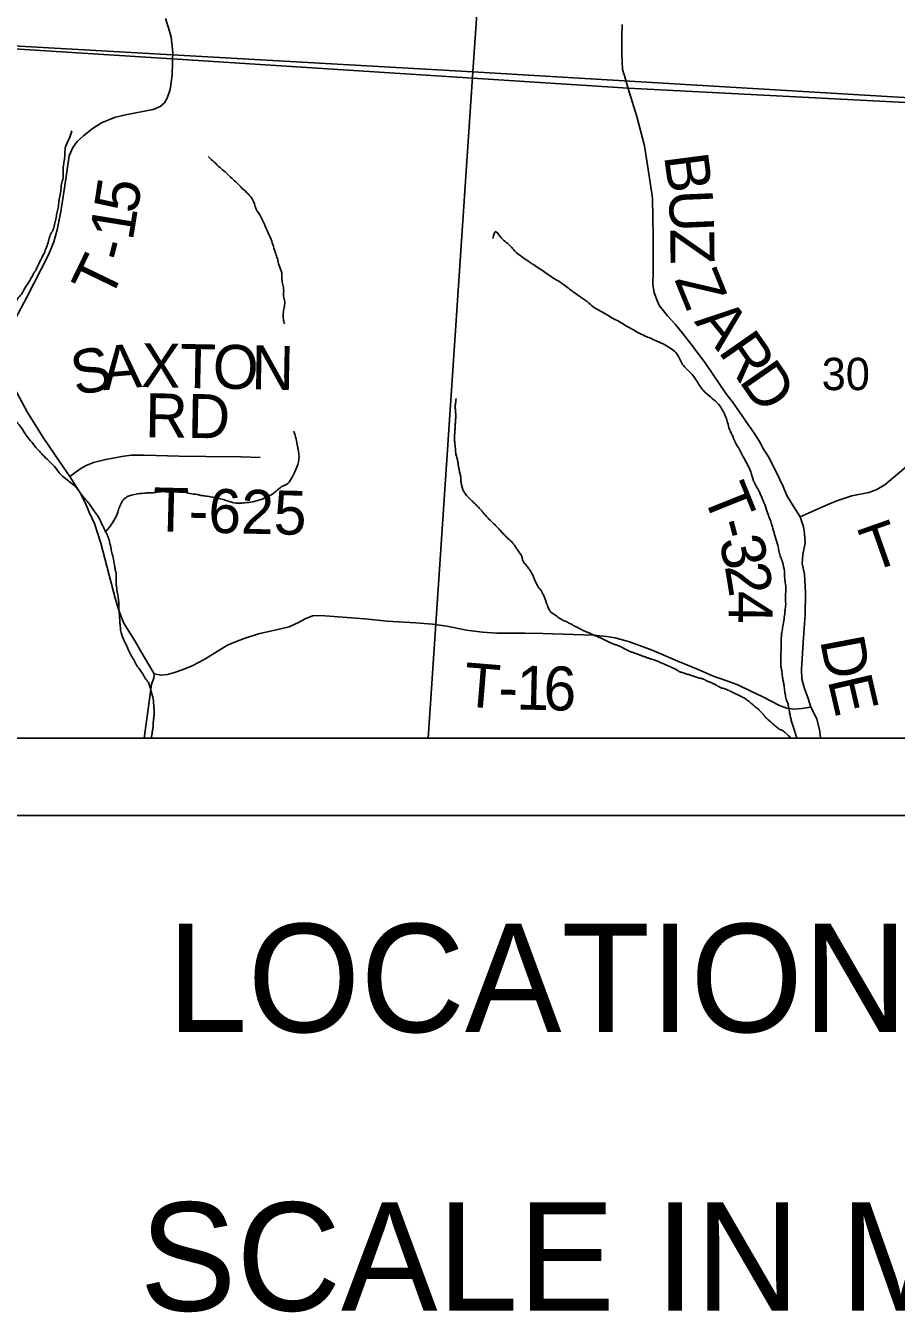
# Model space of a CAD drawing. Extents: x -13.7 to 34, y 0 to 32.3.
# Drawn here: x 26.069 to 27.194, y 13.358 to 15.02 of the extents above; entities that cross this region are included whole.
import ezdxf

# ---------------------------------------------------------------- set-up
doc = ezdxf.new("R2010")
doc.units = 0
for name, color, linetype in [('GM_X_Corporation', 7, 'Continuous'), ('GM_X_Minor_River', 7, 'Continuous'), ('GM_X_Section_Text', 7, 'Continuous'), ('GM_X_Township_Road', 7, 'Continuous'), ('GM_X_Township_Road_Text', 7, 'Continuous'), ('SH_Data', 7, 'Continuous'), ('SH_Text', 7, 'Continuous')]:
    doc.layers.add(name, color=color, linetype=linetype)

msp = doc.modelspace()

# ---------------------------------------------------------------- linework, layer by layer
at = {"layer": 'GM_X_Corporation'}
for points in [[(25.6857, 16.1459), (25.6733, 15.948), (25.6502, 15.5943), (25.6174, 15.0182), (25.5491, 14.1), (30.3167, 14.1)], [(25.6857, 16.1459), (25.6733, 15.948), (25.6502, 15.5943), (25.6174, 15.0182), (26.2581, 14.9774), (26.847, 14.9399), (27.6886, 14.8962), (28.6553, 14.8354)]]:
    msp.add_lwpolyline(points, dxfattribs=at)
for points in [[(25.6876, 16.0444), (26.7165, 15.9781), (26.6464, 14.9606), (25.6185, 15.0191)], [(26.7165, 15.9781), (27.73, 15.9158), (27.6593, 14.9006), (26.6464, 14.9606)], [(25.5491, 14.1), (30.3167, 14.1), (30.3167, 14.7354), (29.7019, 14.7755), (28.6553, 14.8354), (27.6886, 14.8962), (26.847, 14.9399), (26.2581, 14.9774), (25.6174, 15.0182)], [(25.5561, 14.1), (26.5888, 14.1), (26.6464, 14.9606), (25.6185, 15.0191)], [(26.5888, 14.1), (27.607, 14.1), (27.6593, 14.9006), (26.6464, 14.9606)]]:
    msp.add_lwpolyline(points, close=True, dxfattribs=at)
at = {"layer": 'GM_X_Minor_River'}
for points in [[(26.1283, 14.8845), (26.1244, 14.8735), (26.1202, 14.864), (26.1194, 14.8561), (26.119, 14.8496), (26.1178, 14.8424), (26.117, 14.8321), (26.1169, 14.8234), (26.115, 14.8158), (26.1142, 14.8086), (26.1126, 14.7999), (26.1114, 14.7915), (26.1106, 14.785), (26.109, 14.7782), (26.1078, 14.7706), (26.1059, 14.7634), (26.1039, 14.7562), (26.1005, 14.7498), (26.0982, 14.7422), (26.0955, 14.7342), (26.0924, 14.7262), (26.0866, 14.7149), (26.082, 14.7054), (26.0785, 14.6993), (26.0739, 14.691), (26.0686, 14.6827), (26.0632, 14.6736), (26.0582, 14.6675), (26.054, 14.66), (26.0483, 14.6524), (26.0437, 14.6459), (26.0406, 14.6395), (26.0371, 14.6334), (26.0337, 14.6255), (26.0302, 14.6187), (26.0271, 14.6099), (26.0248, 14.6035), (26.0229, 14.5963), (26.0217, 14.5887), (26.0212, 14.5799), (26.0235, 14.5731), (26.0272, 14.5628), (26.0317, 14.554), (26.0366, 14.5472), (26.0392, 14.5407), (26.0429, 14.5327), (26.0467, 14.5251), (26.0515, 14.5163), (26.0572, 14.5083), (26.0628, 14.5014), (26.0681, 14.493), (26.0733, 14.4861), (26.0805, 14.4773), (26.0865, 14.4705), (26.0925, 14.464), (26.1005, 14.4563), (26.1076, 14.4487), (26.1121, 14.4426), (26.1204, 14.4349), (26.1272, 14.4296), (26.1336, 14.4242), (26.1385, 14.4177), (26.1449, 14.4093), (26.1509, 14.4024), (26.1562, 14.3944), (26.1615, 14.3875), (26.1663, 14.3784), (26.1701, 14.3704), (26.1738, 14.3628), (26.1764, 14.3563), (26.1786, 14.3464), (26.1801, 14.3399), (26.182, 14.3308), (26.1834, 14.3236), (26.1845, 14.3175), (26.1856, 14.3114), (26.1856, 14.3023), (26.1863, 14.2931), (26.1877, 14.2848), (26.1888, 14.2775), (26.1891, 14.2688), (26.1898, 14.2593), (26.1902, 14.2532), (26.1909, 14.2444), (26.1916, 14.2384), (26.1946, 14.2285), (26.1976, 14.2224), (26.2024, 14.2117), (26.2058, 14.2052), (26.2099, 14.1983), (26.2133, 14.1922), (26.2189, 14.1846), (26.2227, 14.1777), (26.2272, 14.1716), (26.2305, 14.1613), (26.2328, 14.1534), (26.2339, 14.1469)], [(26.3045, 14.8512), (26.3124, 14.8439), (26.3199, 14.837), (26.3264, 14.8316), (26.3335, 14.8248), (26.3403, 14.8186), (26.3486, 14.8102), (26.3565, 14.8026), (26.3614, 14.7965), (26.3666, 14.7835), (26.3726, 14.7736), (26.376, 14.7667), (26.3805, 14.7557), (26.3857, 14.7442), (26.3887, 14.7355), (26.3917, 14.7256), (26.3939, 14.7195), (26.3961, 14.7107), (26.3995, 14.7012), (26.3998, 14.6947), (26.4005, 14.6871), (26.402, 14.6803), (26.4019, 14.6712), (26.4034, 14.6636), (26.4026, 14.656), (26.4014, 14.6484), (26.4017, 14.6411), (26.4032, 14.635)], [(27.0446, 14.2104), (27.045, 14.2199), (27.045, 14.2271), (27.0455, 14.2347), (27.0467, 14.2423), (27.0482, 14.2515), (27.0494, 14.2606), (27.0502, 14.267), (27.0507, 14.2742), (27.0503, 14.2815), (27.0508, 14.2883), (27.0504, 14.2986), (27.0494, 14.3062), (27.049, 14.3157), (27.0465, 14.3271), (27.0442, 14.334), (27.0424, 14.34), (27.0405, 14.3492), (27.0372, 14.3602), (27.0342, 14.3705), (27.0313, 14.38), (27.0283, 14.388), (27.0246, 14.3991), (27.0204, 14.4094), (27.016, 14.4193), (27.0103, 14.4299), (27.0066, 14.4406), (27.0014, 14.4532), (26.9954, 14.4642), (26.9901, 14.4745), (26.9856, 14.4818), (26.9827, 14.489), (26.9782, 14.4986), (26.9756, 14.5077), (26.9737, 14.5138), (26.9688, 14.5241), (26.9617, 14.5336), (26.9538, 14.5405), (26.944, 14.5493), (26.9357, 14.5615), (26.9297, 14.5699), (26.9214, 14.5783), (26.9165, 14.5844), (26.9131, 14.5913), (26.9086, 14.5982), (26.9015, 14.6039), (26.8947, 14.6081), (26.8852, 14.6124), (26.8776, 14.6159), (26.8705, 14.6189), (26.8621, 14.6228), (26.8531, 14.6278), (26.8436, 14.6332), (26.8342, 14.6389), (26.8259, 14.6431), (26.8183, 14.6478), (26.8092, 14.6528), (26.8032, 14.6562), (26.7964, 14.662), (26.7866, 14.6692), (26.7779, 14.6754), (26.7715, 14.68), (26.7635, 14.6861), (26.7541, 14.6922), (26.7454, 14.6976), (26.7382, 14.703), (26.7303, 14.708), (26.7228, 14.7129), (26.7167, 14.7172), (26.7092, 14.7222), (26.7009, 14.729), (26.6952, 14.7355), (26.6877, 14.742), (26.6816, 14.7482), (26.676, 14.7543), (26.6725, 14.7456)], [(26.172, 14.3664), (26.1873, 14.3904), (26.1892, 14.3965), (26.1919, 14.4029), (26.1965, 14.4094), (26.203, 14.4131), (26.2113, 14.415), (26.2212, 14.4164), (26.228, 14.4168), (26.2345, 14.4171), (26.2432, 14.4182), (26.2504, 14.4186), (26.2565, 14.4189), (26.2637, 14.4189), (26.2724, 14.418), (26.2808, 14.4161), (26.2906, 14.4145), (26.2967, 14.4133), (26.3031, 14.4125), (26.3122, 14.4106), (26.3202, 14.409), (26.3274, 14.4071), (26.3357, 14.4044), (26.3452, 14.4035), (26.352, 14.4039), (26.3619, 14.4053), (26.371, 14.4076), (26.379, 14.4109), (26.3858, 14.4143), (26.3942, 14.4207), (26.4007, 14.4256), (26.4076, 14.429), (26.4129, 14.437), (26.4164, 14.4438), (26.421, 14.4567), (26.4218, 14.4658), (26.4207, 14.4726), (26.4196, 14.4787), (26.4174, 14.489), (26.4152, 14.4966)]]:
    msp.add_spline(points, degree=3, dxfattribs=at)
for points in [[(27.0577, 14.1), (27.0574, 14.1003), (27.0571, 14.1006), (27.0567, 14.1009), (27.0536, 14.1035), (27.0508, 14.1064), (27.0477, 14.1089), (27.0458, 14.1104), (27.0431, 14.1108), (27.0413, 14.1124), (27.0391, 14.1141), (27.037, 14.1159), (27.0348, 14.1177), (27.0322, 14.12), (27.0295, 14.1223), (27.0269, 14.1246), (27.0243, 14.127), (27.0223, 14.1301), (27.0198, 14.1327), (27.0176, 14.1349), (27.0154, 14.1371), (27.013, 14.1392), (27.011, 14.1408), (27.009, 14.1425), (27.0069, 14.1441), (27.0046, 14.1461), (27.0022, 14.148), (26.9998, 14.1499), (26.9968, 14.1521), (26.9933, 14.1536), (26.9899, 14.1553), (26.9878, 14.1563), (26.9857, 14.1573), (26.9835, 14.1583), (26.9811, 14.1595), (26.9787, 14.1607), (26.9763, 14.1618), (26.9729, 14.1634), (26.9692, 14.1642), (26.9657, 14.1657), (26.9625, 14.1671), (26.9595, 14.1692), (26.9563, 14.1707), (26.9541, 14.1717), (26.9517, 14.1724), (26.9495, 14.1734), (26.9474, 14.1743), (26.9456, 14.1757), (26.9434, 14.1764), (26.9413, 14.1772), (26.9391, 14.1773), (26.937, 14.178), (26.9343, 14.1789), (26.9317, 14.1798), (26.929, 14.1807), (26.9243, 14.1823), (26.9194, 14.1836), (26.9147, 14.1854), (26.9116, 14.1865), (26.909, 14.1886), (26.906, 14.19), (26.9008, 14.1923), (26.8956, 14.1946), (26.8905, 14.1969), (26.8884, 14.1978), (26.8864, 14.1987), (26.8844, 14.1996), (26.881, 14.2011), (26.8773, 14.2018), (26.8738, 14.2031), (26.8699, 14.2045), (26.866, 14.2059), (26.8621, 14.2073), (26.8595, 14.2082), (26.857, 14.2091), (26.8545, 14.21), (26.8525, 14.2108), (26.8504, 14.2114), (26.8484, 14.2124), (26.8459, 14.2136), (26.8434, 14.2149), (26.8409, 14.2162), (26.8389, 14.2172), (26.8369, 14.2183), (26.8348, 14.2193), (26.8329, 14.2202), (26.8307, 14.2204), (26.8288, 14.2212), (26.8259, 14.2225), (26.823, 14.2237), (26.8201, 14.2251), (26.8165, 14.2267), (26.813, 14.2285), (26.8095, 14.2301), (26.8066, 14.2314), (26.8037, 14.2327), (26.8008, 14.2339), (26.7987, 14.2349), (26.7965, 14.2357), (26.7944, 14.2366), (26.7913, 14.238), (26.7883, 14.2394), (26.7853, 14.2409), (26.783, 14.242), (26.7807, 14.2432), (26.7785, 14.2443), (26.7757, 14.2458), (26.7729, 14.2474), (26.7702, 14.2489), (26.7675, 14.2504), (26.7645, 14.2513), (26.7618, 14.2528), (26.759, 14.2543), (26.7565, 14.2563), (26.7539, 14.2582), (26.751, 14.2603), (26.7475, 14.2619), (26.7456, 14.2651), (26.744, 14.2679), (26.7431, 14.2709), (26.7419, 14.2738), (26.7401, 14.2783), (26.7385, 14.2828), (26.7366, 14.2872), (26.7351, 14.2908), (26.7317, 14.2935), (26.7299, 14.2971), (26.7286, 14.2997), (26.7274, 14.3024), (26.7261, 14.3051), (26.7252, 14.3071), (26.7245, 14.3092), (26.7235, 14.3112), (26.722, 14.3143), (26.7199, 14.3171), (26.7179, 14.32), (26.7163, 14.3223), (26.7142, 14.3244), (26.7126, 14.3268), (26.7104, 14.3302), (26.71, 14.3345), (26.7078, 14.3379), (26.7064, 14.3399), (26.7051, 14.342), (26.7036, 14.344), (26.7016, 14.347), (26.6997, 14.35), (26.6972, 14.3528), (26.6954, 14.3549), (26.6932, 14.3565), (26.6912, 14.3585), (26.6891, 14.3607), (26.6869, 14.3628), (26.6848, 14.365), (26.6826, 14.3673), (26.6806, 14.3696), (26.6784, 14.3719), (26.6736, 14.377), (26.6685, 14.3817), (26.6637, 14.3868), (26.6609, 14.3897), (26.6586, 14.393), (26.6558, 14.396), (26.6536, 14.3983), (26.6513, 14.4006), (26.649, 14.4029), (26.6465, 14.4053), (26.644, 14.4077), (26.6415, 14.4101), (26.6394, 14.4122), (26.6375, 14.4145), (26.6358, 14.417), (26.6345, 14.419), (26.6336, 14.4212), (26.6328, 14.4235), (26.632, 14.4262), (26.6314, 14.429), (26.631, 14.4318), (26.6307, 14.434), (26.6311, 14.4362), (26.6307, 14.4383), (26.6302, 14.441), (26.6293, 14.4436), (26.6288, 14.4463), (26.6284, 14.4485), (26.6281, 14.4506), (26.6277, 14.4528), (26.6273, 14.4551), (26.627, 14.4573), (26.6266, 14.4596), (26.6261, 14.4626), (26.6247, 14.4654), (26.6244, 14.4684), (26.624, 14.4722), (26.6237, 14.476), (26.6233, 14.4798), (26.6231, 14.4824), (26.6227, 14.4851), (26.6226, 14.4878), (26.6226, 14.4899), (26.6229, 14.4921), (26.6231, 14.4942), (26.6232, 14.4963), (26.6234, 14.4983), (26.6235, 14.5003), (26.6237, 14.5031), (26.6238, 14.5059), (26.6239, 14.5087), (26.6241, 14.5112), (26.6243, 14.5137), (26.6243, 14.5163), (26.6244, 14.5187), (26.6241, 14.5211), (26.624, 14.5235), (26.6239, 14.5256), (26.6234, 14.5278), (26.6237, 14.53), (26.6241, 14.5329), (26.6245, 14.5358), (26.6249, 14.5387)], [(27.0654, 14.1), (27.0648, 14.1012), (27.0643, 14.1023), (27.064, 14.1035), (27.0633, 14.1055), (27.0627, 14.1076), (27.0621, 14.1096), (27.0612, 14.1123), (27.0604, 14.1149), (27.0595, 14.1176), (27.0587, 14.1201), (27.0579, 14.1226), (27.0573, 14.1252), (27.0567, 14.1276), (27.0563, 14.13), (27.0558, 14.1324), (27.0551, 14.1359), (27.0547, 14.1393), (27.054, 14.1427), (27.0534, 14.1453), (27.052, 14.1477), (27.0514, 14.1503), (27.0506, 14.1536), (27.05, 14.1569), (27.0495, 14.1602), (27.0491, 14.1631), (27.0489, 14.1661), (27.0485, 14.169), (27.0481, 14.1714), (27.0473, 14.1738), (27.047, 14.1762), (27.0465, 14.1797), (27.046, 14.1833), (27.0455, 14.1869), (27.0452, 14.1896), (27.0444, 14.1924), (27.0445, 14.1952), (27.0445, 14.1978), (27.0445, 14.2003), (27.0445, 14.2028), (27.0445, 14.2054), (27.0445, 14.2079), (27.0446, 14.2104)], [(26.2339, 14.1469), (26.2341, 14.1436), (26.2343, 14.1403), (26.2345, 14.137), (26.2347, 14.1346), (26.2347, 14.1322), (26.2345, 14.1298), (26.2343, 14.1271), (26.2339, 14.1245), (26.2337, 14.1218), (26.2335, 14.1193), (26.2336, 14.1167), (26.2333, 14.1142), (26.2329, 14.1115), (26.2325, 14.1089), (26.2321, 14.1062), (26.2317, 14.1041), (26.2314, 14.1021), (26.2311, 14.1)]]:
    msp.add_open_spline(points, degree=3, dxfattribs=at)
at = {"layer": 'GM_X_Township_Road'}
for points in [[(26.2493, 15.0297), (26.253, 15.0177), (26.2566, 15.0055), (26.258, 14.994), (26.2586, 14.9854), (26.2583, 14.9769), (26.2582, 14.9748)], [(26.8415, 14.9583), (26.8399, 14.964), (26.8389, 14.9842), (26.8391, 15.0063), (26.8394, 15.0221)], [(26.2582, 14.9748), (26.2582, 14.9728), (26.2578, 14.9566), (26.2552, 14.9379), (26.2515, 14.9268), (26.2479, 14.9207), (26.2424, 14.9158), (26.2336, 14.912), (26.1976, 14.9051), (26.1836, 14.9016), (26.1667, 14.8949), (26.1547, 14.887), (26.1434, 14.8783), (26.1353, 14.8706), (26.1296, 14.8631), (26.125, 14.8521), (26.1182, 14.8081), (26.114, 14.7805), (26.1093, 14.7567), (26.1052, 14.7413), (26.0981, 14.7245), (26.0699, 14.6689), (26.0517, 14.6346)], [(26.8776, 14.8035), (26.8748, 14.8236), (26.8684, 14.8653), (26.8583, 14.9029), (26.8485, 14.9351), (26.8472, 14.9394), (26.8418, 14.9574), (26.8415, 14.9583)], [(27.0956, 14.1), (27.0947, 14.1085), (27.091, 14.1249), (27.0832, 14.1399), (27.0799, 14.1512), (27.0751, 14.1639), (27.0717, 14.1759), (27.071, 14.1886), (27.0732, 14.2236), (27.076, 14.2596), (27.0763, 14.2874), (27.0748, 14.3119), (27.0722, 14.3253), (27.0727, 14.337), (27.076, 14.3517), (27.0751, 14.3641), (27.0736, 14.3728), (27.0693, 14.3857), (27.0581, 14.4035), (27.0523, 14.4133), (27.0473, 14.4248), (27.037, 14.4466), (27.0283, 14.4634), (27.0218, 14.4742), (27.017, 14.4833), (27.0108, 14.4927), (26.9828, 14.5332), (26.9739, 14.5446), (26.9473, 14.5835), (26.9312, 14.6054), (26.9175, 14.6231), (26.9079, 14.6346), (26.8979, 14.6454), (26.8876, 14.6584), (26.884, 14.666), (26.8806, 14.6756), (26.8792, 14.6857), (26.8794, 14.7027), (26.8796, 14.7476), (26.8784, 14.7974), (26.8776, 14.8035)], [(26.0547, 14.5514), (26.0707, 14.5213), (26.0914, 14.4885), (26.1131, 14.456), (26.1259, 14.4381), (26.1389, 14.4168), (26.1454, 14.4042), (26.1503, 14.3927), (26.1574, 14.377), (26.1659, 14.3519), (26.1844, 14.2807), (26.1884, 14.2663), (26.1917, 14.2581), (26.1955, 14.2486), (26.2055, 14.2326), (26.2105, 14.2244), (26.2168, 14.2137), (26.2345, 14.1829), (26.2341, 14.1776), (26.2312, 14.169), (26.2219, 14.1)], [(27.0693, 14.3857), (27.1041, 14.4011), (27.1166, 14.4063), (27.1362, 14.4128), (27.1581, 14.4174), (27.1676, 14.4205), (27.1789, 14.4272), (27.2093, 14.453), (27.2206, 14.462), (27.2351, 14.4712), (27.2525, 14.4807), (27.2721, 14.4918), (27.2988, 14.5043), (27.309, 14.5095), (27.3151, 14.5144), (27.3212, 14.5234), (27.3267, 14.5307)], [(26.1259, 14.4381), (26.1385, 14.4473), (26.1458, 14.4519), (26.1562, 14.4562), (26.1722, 14.46), (26.1929, 14.4639), (26.2051, 14.4657), (26.2219, 14.4656), (26.267, 14.4644), (26.3015, 14.4639), (26.3471, 14.4634), (26.3715, 14.4624)], [(26.2345, 14.1829), (26.2436, 14.1812), (26.2521, 14.1821), (26.2611, 14.1847), (26.2722, 14.1887), (26.2836, 14.1932), (26.3, 14.2019), (26.323, 14.2161), (26.3295, 14.22), (26.3398, 14.2244), (26.3508, 14.2285), (26.3696, 14.2346), (26.3999, 14.2416), (26.4093, 14.2437), (26.4219, 14.2497), (26.43, 14.2541), (26.4391, 14.2577), (26.4497, 14.2584), (26.507, 14.2538), (26.5358, 14.2512), (26.5729, 14.2488), (26.5943, 14.2473), (26.613, 14.2444), (26.6382, 14.2394), (26.659, 14.2367), (26.6773, 14.2356), (26.7137, 14.2354), (26.7367, 14.2351), (26.7763, 14.2337), (26.8022, 14.2327), (26.819, 14.231), (26.8305, 14.2294), (26.8487, 14.2243), (26.878, 14.2135), (26.9113, 14.1994), (26.9374, 14.1886), (26.9561, 14.1804), (26.9748, 14.174), (26.9888, 14.1687), (27.0075, 14.1598), (27.0202, 14.1536), (27.0429, 14.1421), (27.0523, 14.1387), (27.0614, 14.1373), (27.0717, 14.1382), (27.0832, 14.1399)]]:
    msp.add_lwpolyline(points, dxfattribs=at)
at = {"layer": 'SH_Data'}
for points in [[(23.4167, 21), (30.4167, 21), (30.4167, 14), (23.4167, 14)], [(23.5167, 20.9), (30.3167, 20.9), (30.3167, 14.1), (23.5167, 14.1)]]:
    msp.add_lwpolyline(points, close=True, dxfattribs=at)

# ---------------------------------------------------------------- texts
at = {"layer": 'GM_X_Section_Text'}
msp.add_text('30', height=0.04186, rotation=0, dxfattribs=at).set_placement((27.0972, 14.5495))
at = {"layer": 'GM_X_Township_Road_Text'}
for s, height, rotation, p in [('B', 0.0568, 277.4344, (26.8935, 14.8524)), ('5', 0.0568, 81.1398, (26.2126, 14.7764)), ('U', 0.0568, 272.4979, (26.8994, 14.8074)), ('1', 0.0568, 80.771, (26.2069, 14.7414)), ('Z', 0.0568, 270.4736, (26.9016, 14.758)), ('T', 0.0568, 64.1556, (26.1772, 14.6635)), ('-', 0.0568, 75.5462, (26.2, 14.7133)), ('Z', 0.0568, 292.1673, (26.9065, 14.6926)), ('A', 0.0568, 309.0911, (26.9318, 14.6376)), ('R', 0.0568, 304.8517, (26.9627, 14.5996)), ('S', 0.0568, 10.8216, (26.1331, 14.5423)), ('A', 0.0568, 4.9164, (26.1693, 14.5493)), ('X', 0.0568, 358.8889, (26.2175, 14.5535)), ('T', 0.0568, 358.8881, (26.2675, 14.5525)), ('O', 0.0568, 358.888, (26.31, 14.5517)), ('N', 0.0568, 358.8889, (26.36, 14.5507)), ('D', 0.0568, 304.7742, (26.9894, 14.5614)), ('RD', 0.05682, 359.0212, (26.2227, 14.4888)), ('T', 0.0568, 291.8949, (26.9431, 14.4152)), ('T-625', 0.05682, 358.6095, (26.2325, 14.3671)), ('-', 0.0568, 284.7803, (26.9584, 14.3775)), ('T', 0.0568, 19.3782, (27.1608, 14.314)), ('3', 0.0568, 282.8788, (26.9642, 14.3554)), ('2', 0.0568, 279.3648, (26.9718, 14.3222)), ('4', 0.0568, 269.274, (26.9773, 14.2903)), ('D', 0.0568, 280.6955, (27.095, 14.2265)), ('T', 0.0568, 355.2933, (26.6329, 14.1412)), ('1', 0.0568, 358.6937, (26.7023, 14.137)), ('6', 0.0568, 358.4854, (26.7372, 14.1362)), ('E', 0.0568, 283.0711, (27.1048, 14.1749)), ('-', 0.0568, 358.7527, (26.679, 14.1375))]:
    msp.add_text(s, height=height, rotation=rotation, dxfattribs=at).set_placement(p)
at = {"layer": 'SH_Text'}
for s, p in [('LOCATION MAP', (26.2513, 13.72)), ('SCALE IN MILES', (26.216, 13.36))]:
    msp.add_text(s, height=0.14, dxfattribs=at).set_placement(p)

doc.saveas('drawing.dxf')
